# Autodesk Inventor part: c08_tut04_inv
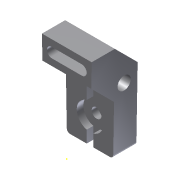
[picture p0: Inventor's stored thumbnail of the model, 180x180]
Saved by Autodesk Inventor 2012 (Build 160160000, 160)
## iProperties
Created: 2010-03
Part Number: c08_tut04_inv
Document SubType Name: Modeling
Designer: CADSoft
Density: 1 g/cm^3
Material: Default
Author: CADSoft
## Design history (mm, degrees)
sketch "Sketch1"
  geometry: 1 further point
sketch "Sketch2"
  geometry: L1 (0, 58)-(14, 58); L2 (28, 44)-(28, 0); L3 (28, 0)-(14, 0); L4 (0, 44)-(0, 58); L5 (0, 44)-(14, 30); L6 (14, 30)-(14, 0); L7 (14, 58)-(28, 44); C1 r 4 at (20, 37); 1 further point
  constraints: 14 end point, 3 parallel, 1 centre point, 1 horizontal, 1 perpendicular, 1 point on line, 1 vertical
  dimensions: "d2" = 14 distance of L4.start L1.start; "d3" = 28 distance between parallel lines of L2 L4; "d4" = 14 distance from line of L2 L1.end; "d5" = 14 distance from line of L2.start L1; "d6" = 58 distance between parallel lines of L3 L1; "d7" = 14 distance of L2.end L3.end; "d8" = 8 diameter of C1; "d9" = 21 distance from line of L1 C1.centre; "d10" = 8 distance from line of L2 C1.centre
extrude "Extrusion1" new body sketch "Sketch2" stored distance "d11" = 30; taper "d12" = 0 deg
sketch "Sketch3"
  geometry: L1 (30, 0)-(0, 0) reference; L2 (30, -30)-(0, -30) reference; L3 (13, 0)-(17, 0); L4 (17, -30)-(13, -30); L5 (13, -7.254)-(13, 0); L6 (17, 0)-(17, -7.254); L7 (13, -30)-(13, -22.746); L8 (17, -22.746)-(17, -30); A1 r 8 centre (15, -15) between (13, -7.254) and (13, -22.746); A2 r 8 centre (15, -15) between (17, -22.746) and (17, -7.254); 2 further points
  constraints: 12 end point, 5 parallel, 4 point on circle, 2 centre point, 2 perpendicular, 2 point on line, 1 horizontal, 1 midpoint
  dimensions: "d13" = 4 distance of L4.start L4.end; "d17" = 8 radius of A1; "d18" = 2 distance from line of L8 A1.centre; "d19" = 15 distance from line of L2 A1.centre
extrude "Extrusion2" cut sketch "Sketch3" distance "d20" = 4; taper "d21" = 0 deg
hole "Hole1" diameter "d24" = 6; stored, may be unused: countersink angle "d28" = 90 deg, drill point angle "d30" = 118 deg; dims "d22" = 10, "d23" = 10, "d25" = 6, "d26" = 4, "d27" = 2, "d29" = 8
sketch "Sketch4"
  geometry: L1 (0, 0)-(30, 0) reference; L2 (30, -14)-(0, -14) reference; L3 (5.49, -4.022)-(24, -4.022); L4 (24, -9.978)-(6, -9.978); A1 r 2.978 centre (24, -7) between (24, -9.978) and (24, -4.022); A2 r 3 centre (6, -6.978) between (5.49, -4.022) and (6, -9.978); 1 further point
  constraints: 4 end point, 4 point on circle, 3 tangent, 2 centre point, 2 parallel
  dimensions: "d31" = 18 distance of A1.centre A2.centre; "d32" = 9 horizontal distance of point (15, -58) A1.centre; "d33" = 7 distance from line of L1 A1.centre; "d34" = 3 radius of A2
extrude "Extrusion3" cut sketch "Sketch4" distance "d35" = 11; taper "d36" = 0 deg
feature "FaceDraft1" dims angle "d37" = 1 deg
fillet "Fillet1" dims "d38" = 2
body "Solid1"
other parameters: "d14" = 2, "d15" = 16
